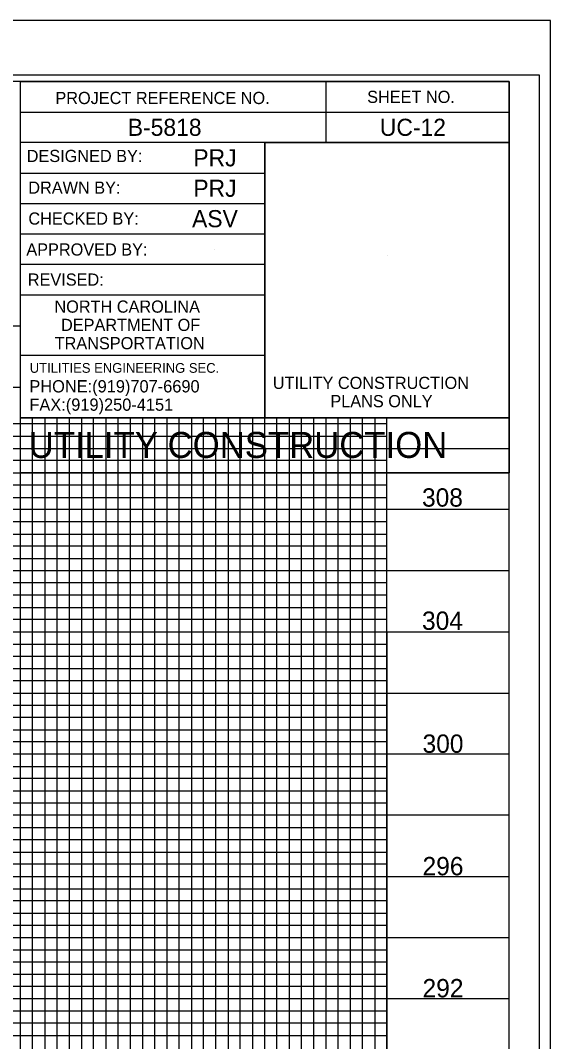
# Model space of a CAD drawing. Extents: x 1439200 to 3815465, y 598050 to 1224643.
# Drawn here: x 3815378.1 to 3815464.9, y 1224476.2 to 1224643.2 of the extents above; entities that cross this region are included whole.
import ezdxf

# ---------------------------------------------------------------- set-up
doc = ezdxf.new("R2010")
doc.units = 0
for name, color, linetype in [('Exist Roads EOP', 7, 'Continuous'), ('General Text and Text Box and Leader Line', 7, 'Continuous'), ('Pattern 49', 7, 'Continuous'), ('Profile Utility Text', 7, 'Continuous'), ('Prop 8 In Water Line (St)', 7, 'Continuous'), ('Scratch_Level_1', 7, 'Continuous'), ('Scratch_Level_9', 7, 'Continuous'), ('UE Detail Plan Sheet w Clip 34 CELL', 7, 'Continuous')]:
    doc.layers.add(name, color=color, linetype=linetype)

msp = doc.modelspace()

# ---------------------------------------------------------------- linework, layer by layer
at = {"layer": 'Exist Roads EOP'}
for p, q in [((3815378.11, 1224623.19), (3815378.13, 1224633.21)), ((3815378.13, 1224633.21), (3815458.11, 1224633.21)), ((3815378.13, 1224623.25), (3815378.13, 1224633.21)), ((3815428.14, 1224633.19), (3815428.14, 1224623.23)), ((3815458.11, 1224633.21), (3815458.11, 1224623.25)), ((3815378.13, 1224628.21), (3815458.13, 1224628.21)), ((3815403.13, 1224625.73), (3815403.13, 1224625.73)), ((3815443.12, 1224625.73), (3815443.12, 1224625.73)), ((3815458.11, 1224623.25), (3815378.13, 1224623.25)), ((3815409.94, 1224620.74), (3815409.94, 1224620.74)), ((3815378.13, 1224618.25), (3815418.14, 1224618.25)), ((3815409.94, 1224615.76), (3815409.94, 1224615.76)), ((3815378.13, 1224613.27), (3815418.14, 1224613.27)), ((3815409.94, 1224610.79), (3815409.94, 1224610.79)), ((3815378.13, 1224608.29), (3815418.14, 1224608.29)), ((3815409.94, 1224605.81), (3815409.94, 1224605.81)), ((3815438.13, 1224604.75), (3815438.13, 1224604.75)), ((3815378.13, 1224603.32), (3815418.14, 1224603.32)), ((3815378.13, 1224598.33), (3815418.14, 1224598.33)), ((3815378.13, 1224588.46), (3815418.14, 1224588.46)), ((3815438.11, 1224561.21), (3814878.11, 1224561.21)), ((3814878.11, 1224559.21), (3815438.11, 1224559.21)), ((3815438.11, 1224551.21), (3814878.11, 1224551.21))]:
    msp.add_line(p, q, dxfattribs=at)
for points in [[(3815458.11, 1224633.21), (3814858.11, 1224633.21), (3814858.11, 1224213.21), (3815458.11, 1224213.21)], [(3814878.11, 1224633.21), (3814878.11, 1224223.21), (3815438.11, 1224223.21), (3815438.11, 1224578.19), (3815378.11, 1224578.19), (3815378.11, 1224633.21)], [(3815418.14, 1224623.25), (3815458.11, 1224623.25), (3815458.11, 1224578.19), (3815418.14, 1224578.19)]]:
    msp.add_lwpolyline(points, close=True, dxfattribs=at)
for points in [[(3815378.11, 1224223.21), (3815378.11, 1224633.21), (3815388.63, 1224633.21)], [(3815418.14, 1224623.25), (3815418.14, 1224578.19), (3815378.11, 1224578.19), (3815378.11, 1224633.21), (3815418.14, 1224633.21), (3815418.14, 1224633.15)], [(3815378.09, 1224593.21), (3814858.11, 1224593.21), (3814858.11, 1224573.19), (3815458.11, 1224573.19)], [(3815458.11, 1224563.21), (3814858.11, 1224563.21), (3814858.11, 1224583.21), (3815378.09, 1224583.21)], [(3815380.11, 1224223.21), (3815380.11, 1224578.19)], [(3815382.11, 1224578.19), (3815382.11, 1224223.21), (3815384.11, 1224223.21), (3815384.11, 1224578.19)], [(3815386.11, 1224578.19), (3815386.11, 1224223.21), (3815390.11, 1224223.21), (3815390.11, 1224578.19)], [(3815388.11, 1224578.19), (3815388.11, 1224223.21), (3815408.11, 1224223.21), (3815408.11, 1224578.19)], [(3815392.11, 1224578.19), (3815392.11, 1224223.21), (3815394.11, 1224223.21), (3815394.11, 1224578.19)], [(3815396.11, 1224578.19), (3815396.11, 1224223.21), (3815400.11, 1224223.21), (3815400.11, 1224578.19)], [(3815398.11, 1224578.19), (3815398.11, 1224223.21), (3815418.11, 1224223.21), (3815418.11, 1224578.19)], [(3815402.11, 1224578.19), (3815402.11, 1224223.21), (3815404.11, 1224223.21), (3815404.11, 1224578.19)], [(3815406.11, 1224578.19), (3815406.11, 1224223.21), (3815410.11, 1224223.21), (3815410.11, 1224578.19)], [(3815412.11, 1224578.19), (3815412.11, 1224223.21)], [(3815412.11, 1224223.21), (3815414.11, 1224223.21), (3815414.11, 1224578.19)], [(3815416.11, 1224578.19), (3815416.11, 1224223.21), (3815420.11, 1224223.21), (3815420.11, 1224578.19)], [(3815422.11, 1224578.19), (3815422.11, 1224223.21), (3815424.11, 1224223.21), (3815424.11, 1224578.19)], [(3815426.11, 1224578.19), (3815426.11, 1224223.21), (3815430.11, 1224223.21), (3815430.11, 1224578.19)], [(3815428.11, 1224578.19), (3815428.11, 1224223.21)], [(3815432.11, 1224578.19), (3815432.11, 1224223.21), (3815434.11, 1224223.21), (3815434.11, 1224578.19)], [(3815436.11, 1224578.19), (3815436.11, 1224223.21), (3815440.11, 1224223.21)], [(3815438.11, 1224577.21), (3814878.11, 1224577.21), (3814878.11, 1224577.21), (3814878.11, 1224569.21), (3815438.11, 1224569.21)], [(3815438.11, 1224577.21), (3814878.11, 1224577.21), (3814878.11, 1224577.21), (3814878.11, 1224569.21), (3815458.11, 1224569.21)], [(3814878.11, 1224575.21), (3815438.11, 1224575.21)], [(3815438.11, 1224571.21), (3814878.11, 1224571.21)], [(3815438.11, 1224567.21), (3814878.11, 1224567.21), (3814878.11, 1224565.21), (3815438.11, 1224565.21)], [(3815438.11, 1224557.21), (3814878.11, 1224557.21), (3814878.11, 1224555.21), (3815438.11, 1224555.21)], [(3815458.11, 1224553.21), (3814858.11, 1224553.21), (3814858.11, 1224533.21), (3815458.11, 1224533.21)], [(3815438.11, 1224549.21), (3814878.11, 1224549.21), (3814878.11, 1224547.21), (3815438.11, 1224547.21)], [(3815438.11, 1224545.21), (3814878.11, 1224545.21)], [(3815458.11, 1224523.21), (3814858.11, 1224523.21), (3814858.11, 1224543.21), (3815458.11, 1224543.21)], [(3815438.11, 1224543.21), (3815438.11, 1224223.21)], [(3814878.11, 1224541.21), (3815438.11, 1224541.21)], [(3815438.11, 1224539.21), (3814878.11, 1224539.21), (3814878.11, 1224537.21), (3815438.11, 1224537.21)], [(3815438.11, 1224535.21), (3814878.11, 1224535.21), (3814878.11, 1224531.21), (3815438.11, 1224531.21)], [(3815438.11, 1224529.21), (3814878.11, 1224529.21), (3814878.11, 1224527.21), (3815438.11, 1224527.21)], [(3815438.11, 1224525.21), (3814878.11, 1224525.21), (3814878.11, 1224521.21), (3815438.11, 1224521.21)], [(3815438.11, 1224519.21), (3814878.11, 1224519.21), (3814878.11, 1224517.21), (3815438.11, 1224517.21)], [(3815438.11, 1224515.21), (3814878.11, 1224515.21), (3814878.11, 1224511.21), (3815438.11, 1224511.21)], [(3815458.11, 1224513.21), (3814858.11, 1224513.21), (3814858.11, 1224493.21), (3815458.11, 1224493.21)], [(3815438.11, 1224509.21), (3814878.11, 1224509.21), (3814878.11, 1224507.21), (3815438.11, 1224507.21)], [(3815438.11, 1224505.21), (3814878.11, 1224505.21), (3814878.11, 1224501.21), (3815438.11, 1224501.21)], [(3815458.11, 1224483.21), (3814858.11, 1224483.21), (3814858.11, 1224503.21), (3815458.11, 1224503.21)], [(3815438.11, 1224499.21), (3814878.11, 1224499.21), (3814878.11, 1224497.21), (3815438.11, 1224497.21)], [(3815438.11, 1224495.21), (3814878.11, 1224495.21), (3814878.11, 1224491.21), (3815438.11, 1224491.21)], [(3815438.11, 1224489.21), (3814878.11, 1224489.21), (3814878.11, 1224487.21), (3815438.11, 1224487.21)], [(3815438.11, 1224485.21), (3814878.11, 1224485.21), (3814878.11, 1224481.21), (3815438.11, 1224481.21)], [(3815438.11, 1224479.21), (3814878.11, 1224479.21), (3814878.11, 1224477.21), (3815438.11, 1224477.21)]]:
    msp.add_lwpolyline(points, dxfattribs=at)
at = {"layer": 'Pattern 49'}
msp.add_lwpolyline([(3815463.11, 1224634.23), (3814796.51, 1224634.23), (3814796.51, 1224212.19), (3815463.11, 1224212.19)], close=True, dxfattribs=at)
at = {"layer": 'Profile Utility Text'}
msp.add_lwpolyline([(3815378.11, 1224578.19), (3815458.11, 1224578.19), (3815458.11, 1224569.21), (3815416.02, 1224569.21), (3815402.09, 1224569.21), (3815378.11, 1224569.21)], close=True, dxfattribs=at)
at = {"layer": 'Scratch_Level_1'}
msp.add_lwpolyline([(3815464.91, 1224643.21), (3814791.31, 1224643.21), (3814791.31, 1224203.21), (3815464.91, 1224203.21)], close=True, dxfattribs=at)
at = {"layer": 'UE Detail Plan Sheet w Clip 34 CELL'}
msp.add_lwpolyline([(3815378.11, 1224578.19), (3815458.11, 1224578.19), (3815458.11, 1224569.21), (3815378.11, 1224569.21)], close=True, dxfattribs=at)

# ---------------------------------------------------------------- texts
at = {"layer": 'Exist Roads EOP'}
for s, height, p in [('PROJECT REFERENCE NO.', 1.9916, (3815383.85, 1224629.53)), ('SHEET NO.', 1.992, (3815434.88, 1224629.71)), ('DESIGNED BY:', 1.9916, (3815379.15, 1224620.05)), ('DRAWN BY:', 1.992, (3815379.41, 1224614.87)), ('CHECKED BY:', 1.9916, (3815379.43, 1224609.81)), ('APPROVED BY:', 1.9916, (3815379.09, 1224604.75)), ('REVISED:', 1.992, (3815379.33, 1224599.83)), ('NORTH CAROLINA', 1.9916, (3815383.69, 1224595.41)), ('DEPARTMENT OF', 1.9916, (3815384.77, 1224592.42)), ('TRANSPORTATION', 1.9916, (3815383.73, 1224589.43)), ('UTILITIES ENGINEERING SEC.', 1.5933, (3815379.65, 1224585.58)), ('UTILITY CONSTRUCTION', 1.9916, (3815419.44, 1224582.94)), ('PLANS ONLY', 1.992, (3815428.86, 1224579.95))]:
    msp.add_text(s, height=height, rotation=360, dxfattribs=at).set_placement(p)
at = {"layer": 'General Text and Text Box and Leader Line'}
for s, p in [('308', (3815443.86, 1224563.69)), ('304', (3815443.86, 1224543.54)), ('300', (3815443.95, 1224523.43)), ('296', (3815443.95, 1224503.4)), ('292', (3815443.95, 1224483.44))]:
    msp.add_text(s, height=3, dxfattribs=at).set_placement(p)
at = {"layer": 'Prop 8 In Water Line (St)'}
for s, p in [('B-5818', (3815395.7, 1224624.33)), ('UC-12', (3815436.96, 1224624.33)), ('PRJ', (3815406.43, 1224619.34)), ('PRJ', (3815406.43, 1224614.36)), ('ASV', (3815406.22, 1224609.39))]:
    msp.add_text(s, height=2.8, dxfattribs=at).set_placement(p)
at = {"layer": 'Scratch_Level_9'}
for s, p in [('PHONE:(919)707-6690', (3815379.59, 1224582.37)), ('FAX:(919)250-4151', (3815379.59, 1224579.37))]:
    msp.add_text(s, height=2.0046, rotation=360, dxfattribs=at).set_placement(p)
at = {"layer": 'UE Detail Plan Sheet w Clip 34 CELL'}
msp.add_text('UTILITY CONSTRUCTION', height=4.25, rotation=360, dxfattribs=at).set_placement((3815379.48, 1224571.66))

doc.saveas('drawing.dxf')
